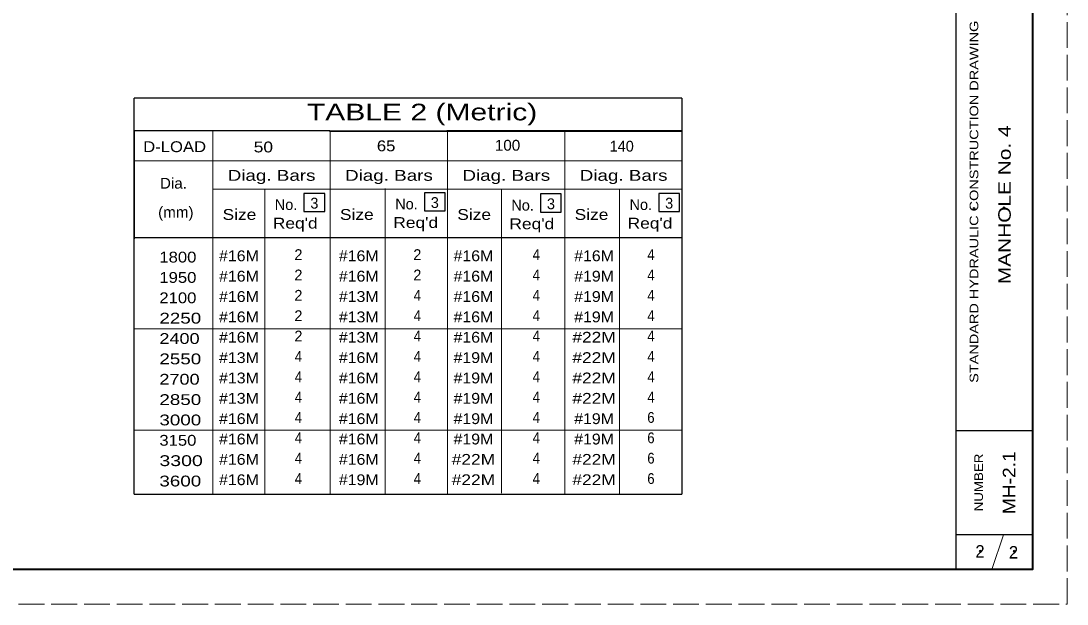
# Model space of a CAD drawing. Extents: x 1170.6 to 1204.6, y 975 to 1019.
# Drawn here: x 1189.51 to 1204.59, y 975.03 to 983.44 of the extents above; entities that cross this region are included whole.
import ezdxf
from ezdxf.enums import TextEntityAlignment as Align

# ---------------------------------------------------------------- set-up
doc = ezdxf.new("R2010")
doc.units = 0
doc.header["$LTSCALE"] = 0.062
doc.header["$PDMODE"] = 32
doc.header["$PDSIZE"] = 0.031
doc.linetypes.add('LONG_DASHED', pattern=[7.5, 6, -1.5])
doc.layers.add('1', color=7, linetype='Continuous', lineweight=13)

msp = doc.modelspace()

# ---------------------------------------------------------------- linework, layer by layer
at = {"layer": '1', "lineweight": 25}
for p, q in [((1202.99275, 975.52625), (1202.99275, 996.52625)), ((1204.09275, 996.52625), (1204.09275, 975.52625)), ((1199.038, 982.32592), (1191.14158, 982.32592)), ((1191.14158, 980.293), (1191.14158, 982.32592)), ((1193.956, 981.85042), (1195.65367, 981.85042)), ((1197.34583, 981.85392), (1195.64817, 981.85392)), ((1195.64817, 981.85042), (1197.34583, 981.85042)), ((1199.038, 981.85392), (1197.34042, 981.85392)), ((1197.34042, 981.85042), (1199.038, 981.85042)), ((1191.14158, 976.61342), (1191.14158, 980.293)), ((1191.14483, 980.31667), (1193.02375, 980.31667)), ((1193.01917, 980.31667), (1193.96467, 980.31667)), ((1193.956, 980.31667), (1194.71592, 980.31667)), ((1194.71133, 980.31667), (1195.65683, 980.31667)), ((1195.64817, 980.31667), (1196.40817, 980.31667)), ((1196.40358, 980.31667), (1197.34908, 980.31667)), ((1197.34042, 980.31667), (1198.10033, 980.31667)), ((1198.09575, 980.31667), (1199.04125, 980.31667)), ((1204.09275, 977.52625), (1202.99275, 977.52625)), ((1191.14158, 976.61342), (1199.038, 976.61342)), ((1204.09275, 976.02625), (1202.99275, 976.02625))]:
    msp.add_line(p, q, dxfattribs=at)
at = {"layer": '1'}
for p, q in [((1193.956, 982.32242), (1195.65367, 982.32242)), ((1195.64817, 982.32242), (1197.34583, 982.32242)), ((1197.34042, 982.32242), (1199.038, 982.32242)), ((1195.65367, 981.85392), (1193.956, 981.85392)), ((1191.14483, 981.42092), (1193.96142, 981.42092)), ((1193.956, 981.42092), (1195.65367, 981.42092)), ((1195.64817, 981.42092), (1197.34583, 981.42092)), ((1197.34042, 981.42092), (1199.038, 981.42092)), ((1192.2725, 981.0125), (1193.02375, 981.0125)), ((1193.01917, 981.0125), (1193.96467, 981.0125)), ((1193.96467, 981.0125), (1194.71592, 981.0125)), ((1194.71133, 981.0125), (1195.65683, 981.0125)), ((1195.65683, 981.0125), (1196.40817, 981.0125)), ((1196.40358, 981.0125), (1197.34908, 981.0125)), ((1196.43508, 981.0035), (1196.43508, 980.284)), ((1197.34908, 981.0125), (1198.10033, 981.0125)), ((1198.09575, 981.0125), (1199.04125, 981.0125)), ((1196.43467, 980.30808), (1196.43467, 976.6285)), ((1191.14483, 978.999), (1199.038, 978.999)), ((1191.14483, 977.53733), (1199.038, 977.53733)), ((1203.50942, 975.52625), (1203.67608, 976.02625))]:
    msp.add_line(p, q, dxfattribs=at)
at = {"layer": '1', "linetype": 'LONG_DASHED'}
msp.add_lwpolyline([(1170.59275, 975.02625), (1204.59275, 975.02625), (1204.59275, 997.02625), (1170.59275, 997.02625)], close=True, dxfattribs=at)
at = {"layer": '1', "lineweight": 25}
for points in [[(1204.09275, 975.52625), (1172.59275, 975.52625), (1172.59275, 996.52625)], [(1199.038, 982.32592), (1199.038, 980.293), (1199.038, 976.61342)], [(1193.96142, 981.85392), (1191.14158, 981.85392), (1191.14158, 980.293)]]:
    msp.add_lwpolyline(points, dxfattribs=at)
at = {"layer": '1', "lineweight": 40}
msp.add_lwpolyline([(1172.59275, 996.52625), (1204.09275, 996.52625), (1204.09275, 975.52625), (1172.59275, 975.52625)], close=True, dxfattribs=at)
at = {"layer": '1'}
for points in [[(1192.2725, 981.85392), (1192.2725, 980.293), (1192.2725, 976.61342)], [(1193.96467, 981.85392), (1193.96467, 980.293), (1193.96467, 976.61342)], [(1195.65683, 981.85392), (1195.65683, 980.293), (1195.65683, 976.61342)], [(1197.34908, 981.85392), (1197.34908, 980.293), (1197.34908, 976.61342)], [(1193.02375, 981.0125), (1193.02375, 980.293), (1193.02375, 976.61342)], [(1194.76092, 981.0215), (1194.76092, 980.302), (1194.76092, 976.62242)], [(1198.13967, 981.0125), (1198.13967, 980.293), (1198.13967, 976.61342)]]:
    msp.add_lwpolyline(points, dxfattribs=at)
at = {"layer": '1', "lineweight": 25}
for points in [[(1193.58858, 980.95133), (1193.58858, 980.68958), (1193.88725, 980.68958), (1193.88725, 980.95133)], [(1195.32575, 980.96033), (1195.32575, 980.69858), (1195.62442, 980.69858), (1195.62442, 980.96033)], [(1197, 980.94233), (1197, 980.68058), (1197.29867, 980.68058), (1197.29867, 980.94233)], [(1198.7045, 980.95133), (1198.7045, 980.68958), (1199.00317, 980.68958), (1199.00317, 980.95133)]]:
    msp.add_lwpolyline(points, close=True, dxfattribs=at)
at = {"layer": '1'}
for p in [(1203.25017, 980.73225), (1203.683, 980.73958), (1203.34083, 975.79), (1203.82925, 975.789)]:
    msp.add_point(p, dxfattribs=at)

# ---------------------------------------------------------------- texts
for s, height, width, p in [('STANDARD HYDRAULIC CONSTRUCTION DRAWING', 0.125, 1.25, (1203.31267, 980.83029)), ('MANHOLE No. 4', 0.18, 1.25, (1203.78058, 980.78638)), ('NUMBER', 0.125, 1.15, (1203.37975, 976.78033)), ('MH-2.1', 0.18, 1.15, (1203.84625, 976.77662))]:
    msp.add_text(s, height=height, rotation=90, dxfattribs=dict(at, width=width)).set_placement(p, align=Align.CENTER)
for s, height, width, p in [('TABLE 2 (Metric)', 0.24, 1.35, (1193.63042, 982.00458)), ('D-LOAD', 0.156, 1.15, (1191.27033, 981.54658)), ('50', 0.156, 1.2, (1192.86392, 981.54242)), ('65', 0.156, 1.15, (1194.64, 981.55875)), ('100', 0.156, 1.05, (1196.3415, 981.567)), ('Dia.', 0.156, 1.05, (1191.51158, 981.01917)), ('Diag. Bars', 0.156, 1.3, (1192.48875, 981.13267)), ('Diag. Bars', 0.156, 1.3, (1194.18092, 981.13267)), ('Diag. Bars', 0.156, 1.3, (1195.87308, 981.13267)), ('Diag. Bars', 0.156, 1.3, (1197.56533, 981.13267)), ('(mm)', 0.156, 1.05, (1191.48542, 980.60258)), ('Size', 0.156, 1.2, (1192.41492, 980.56875)), ('Size', 0.156, 1.2, (1194.10717, 980.56875)), ('Size', 0.156, 1.2, (1195.79933, 980.56875)), ('Size', 0.156, 1.2, (1197.4915, 980.56875)), ("Req'd", 0.156, 1.2, (1193.13958, 980.4435)), ("Req'd", 0.156, 1.2, (1194.87675, 980.4525)), ("Req'd", 0.156, 1.2, (1196.551, 980.4345)), ("Req'd", 0.156, 1.2, (1198.2555, 980.4435)), ('1800', 0.156, 1.15, (1191.5035, 979.95375)), ('1950', 0.156, 1.15, (1191.5035, 979.66008)), ('2100', 0.156, 1.15, (1191.5035, 979.36642)), ('2250', 0.156, 1.3, (1191.5035, 979.07275)), ('2400', 0.156, 1.25, (1191.5035, 978.77908)), ('2550', 0.156, 1.3, (1191.5035, 978.48542)), ('2700', 0.156, 1.25, (1191.5035, 978.19175)), ('2850', 0.156, 1.3, (1191.5035, 977.89808)), ('3000', 0.156, 1.3, (1191.5035, 977.60442)), ('3150', 0.156, 1.15, (1191.5035, 977.31075)), ('3300', 0.156, 1.35, (1191.5035, 977.01708)), ('3600', 0.156, 1.3, (1191.5035, 976.72342))]:
    msp.add_text(s, height=height, dxfattribs=dict(at, width=width)).set_placement(p)
for s, p in [('140', (1197.99642, 981.55392)), ('3', (1193.68075, 980.73158)), ('3', (1195.41792, 980.74058)), ('3', (1197.09217, 980.7225)), ('3', (1198.79667, 980.73158)), ('No.', (1193.1675, 980.71108)), ('No.', (1194.90467, 980.72008)), ('No.', (1196.57892, 980.70208)), ('No.', (1198.28342, 980.71108))]:
    msp.add_text(s, height=0.156, dxfattribs=at).set_placement(p)
for s, width, p in [('#16M', 1.1, (1192.651, 979.97225)), ('#16M', 1.1, (1194.37825, 979.97225)), ('#16M', 1.1, (1196.032, 979.97225)), ('4', 0.9, (1196.93837, 979.9895)), ('#16M', 1.1, (1197.77142, 979.97225)), ('4', 0.9, (1198.59212, 979.9895)), ('#16M', 1.1, (1192.651, 979.67858)), ('#16M', 1.1, (1194.37825, 979.67858)), ('#16M', 1.1, (1196.032, 979.67858)), ('4', 0.9, (1196.93837, 979.69583)), ('#19M', 1.1, (1197.77146, 979.67858)), ('4', 0.9, (1198.59212, 979.69583)), ('#16M', 1.1, (1192.651, 979.38492)), ('#13M', 1.1, (1194.37825, 979.38492)), ('4', 0.9, (1195.22346, 979.40217)), ('#16M', 1.1, (1196.032, 979.38492)), ('4', 0.9, (1196.93837, 979.40217)), ('#19M', 1.1, (1197.77146, 979.38492)), ('4', 0.9, (1198.59212, 979.40217)), ('#16M', 1.1, (1192.651, 979.09125)), ('#13M', 1.1, (1194.37825, 979.09125)), ('4', 0.9, (1195.22346, 979.1085)), ('#16M', 1.1, (1196.032, 979.09125)), ('4', 0.9, (1196.93837, 979.1085)), ('#19M', 1.1, (1197.77146, 979.09125)), ('4', 0.9, (1198.59212, 979.1085)), ('#16M', 1.1, (1192.651, 978.79758)), ('#13M', 1.1, (1194.37825, 978.79758)), ('4', 0.9, (1195.22346, 978.81483)), ('#16M', 1.1, (1196.032, 978.79758)), ('4', 0.9, (1196.93837, 978.81483)), ('#22M', 1.2, (1197.77142, 978.79758)), ('4', 0.9, (1198.59212, 978.81483)), ('#13M', 1.1, (1192.651, 978.50392)), ('4', 0.9, (1193.50846, 978.52117)), ('#16M', 1.1, (1194.37825, 978.50392)), ('4', 0.9, (1195.22346, 978.52117)), ('#19M', 1.1, (1196.03204, 978.50392)), ('4', 0.9, (1196.93837, 978.52117)), ('#22M', 1.2, (1197.77142, 978.50392)), ('4', 0.9, (1198.59212, 978.52117)), ('#13M', 1.1, (1192.651, 978.21025)), ('4', 0.9, (1193.50846, 978.2275)), ('#16M', 1.1, (1194.37825, 978.21025)), ('4', 0.9, (1195.22346, 978.2275)), ('#19M', 1.1, (1196.03204, 978.21025)), ('4', 0.9, (1196.93837, 978.2275)), ('#22M', 1.2, (1197.77142, 978.21025)), ('4', 0.9, (1198.59212, 978.2275)), ('#13M', 1.1, (1192.651, 977.91658)), ('4', 0.9, (1193.50846, 977.93383)), ('#16M', 1.1, (1194.37825, 977.91658)), ('4', 0.9, (1195.22346, 977.93383)), ('#19M', 1.1, (1196.03204, 977.91658)), ('4', 0.9, (1196.93837, 977.93383)), ('#22M', 1.2, (1197.77142, 977.91658)), ('4', 0.9, (1198.59212, 977.93383)), ('#16M', 1.1, (1192.651, 977.62292)), ('4', 0.9, (1193.50846, 977.64017)), ('#16M', 1.1, (1194.37825, 977.62292)), ('4', 0.9, (1195.22346, 977.64017)), ('#19M', 1.1, (1196.03204, 977.62292)), ('4', 0.9, (1196.93837, 977.64017)), ('#19M', 1.1, (1197.77146, 977.62292)), ('6', 0.9, (1198.59212, 977.64017)), ('#16M', 1.1, (1192.651, 977.32925)), ('4', 0.9, (1193.50846, 977.3465)), ('#16M', 1.1, (1194.37825, 977.32925)), ('4', 0.9, (1195.22346, 977.3465)), ('#19M', 1.1, (1196.03204, 977.32925)), ('4', 0.9, (1196.93837, 977.3465)), ('#19M', 1.1, (1197.77146, 977.32925)), ('6', 0.9, (1198.59212, 977.3465)), ('#16M', 1.1, (1192.651, 977.03558)), ('4', 0.9, (1193.50846, 977.05283)), ('#16M', 1.1, (1194.37825, 977.03558)), ('4', 0.9, (1195.22346, 977.05283)), ('#22M', 1.2, (1196.032, 977.03558)), ('4', 0.9, (1196.93837, 977.05283)), ('#22M', 1.2, (1197.77142, 977.03558)), ('6', 0.9, (1198.59212, 977.05283)), ('#16M', 1.1, (1192.651, 976.74192)), ('4', 0.9, (1193.50846, 976.75917)), ('#19M', 1.1, (1194.37829, 976.74192)), ('4', 0.9, (1195.22346, 976.75917)), ('#22M', 1.2, (1196.032, 976.74192)), ('4', 0.9, (1196.93837, 976.75917)), ('#22M', 1.2, (1197.77142, 976.74192)), ('6', 0.9, (1198.59212, 976.75917))]:
    msp.add_text(s, height=0.156, dxfattribs=dict(at, width=width)).set_placement(p, align=Align.CENTER)
for height, p in [(0.156, (1193.50854, 979.9895)), (0.156, (1195.22354, 979.9895)), (0.156, (1193.50854, 979.69583)), (0.156, (1195.22354, 979.69583)), (0.156, (1193.50854, 979.40217)), (0.156, (1193.50854, 979.1085)), (0.156, (1193.50854, 978.81483)), (0.18, (1203.33721, 975.69633)), (0.18, (1203.82004, 975.68375))]:
    msp.add_text('2', height=height, dxfattribs=at).set_placement(p, align=Align.CENTER)

doc.saveas('drawing.dxf')
